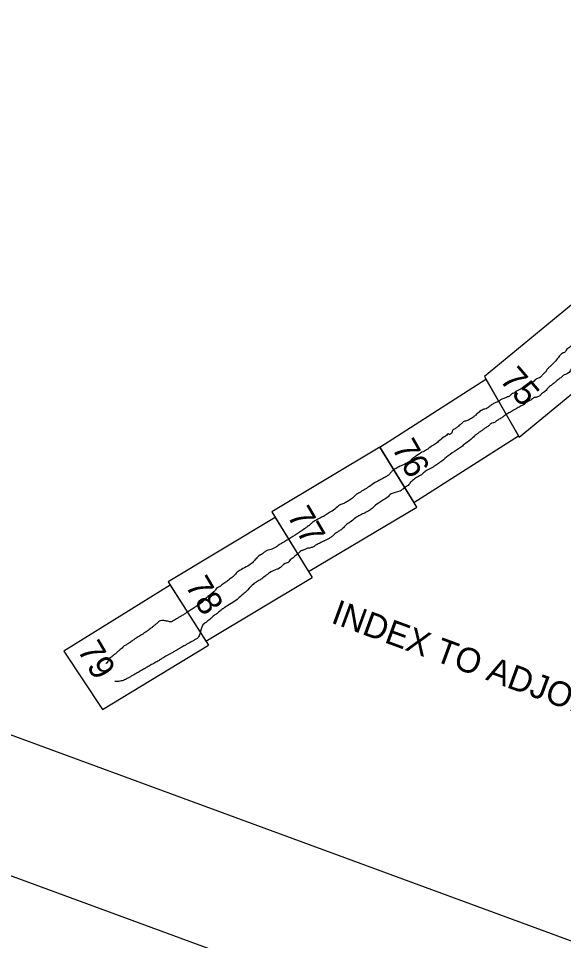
# Model space of a CAD drawing. Extents: x 3972907 to 3994831, y 172639 to 190852.
# Drawn here: x 3984065 to 3985354, y 175090 to 177268 of the extents above; entities that cross this region are included whole.
import ezdxf

# ---------------------------------------------------------------- set-up
doc = ezdxf.new("R2010")
doc.units = 0
for name, color, linetype in [('G-ANNO-NPLT', 7, 'Continuous'), ('V-ANNO-NPLT', 7, 'Continuous'), ('V-ANNO-SYMB', 7, 'Continuous')]:
    doc.layers.add(name, color=color, linetype=linetype)

msp = doc.modelspace()

# ---------------------------------------------------------------- linework, layer by layer
at = {"layer": 'G-ANNO-NPLT'}
msp.add_lwpolyline([(3973180.8, 179237.2), (3990388.6, 172912.5), (3994557.2, 184254), (3977349.3, 190578.7)], close=True, dxfattribs=at)
at = {"layer": 'V-ANNO-NPLT'}
msp.add_line((3984424, 175929.3), (3984514.7, 175787.9), dxfattribs=at)
for points in [[(3985380.7, 176598.4), (3985166.5, 176422.1)], [(3985166.5, 176422.1), (3985248.9, 176278.6), (3985484.6, 176472.4)], [(3984919.3, 176255), (3985170.1, 176415.7)], [(3985170.1, 176415.7), (3985247, 176281.9)], [(3985000.1, 176124.3), (3985247, 176281.9)], [(3984919.3, 176255), (3984663.9, 176102.4)], [(3984919.3, 176255), (3985000.1, 176124.3)], [(3985006.9, 176113.3), (3984919.3, 176255)], [(3984663.9, 176102.4), (3984751.1, 175961.5), (3985006.9, 176113.3)], [(3984672.3, 176088.9), (3984418.9, 175937.2), (3984508.6, 175797.3)], [(3984672.3, 176088.9), (3984759.7, 175947.5)], [(3984508.6, 175797.3), (3984759.7, 175947.5)], [(3984424, 175929.3), (3984172.6, 175773.6), (3984264, 175635.8), (3984514.7, 175787.9)]]:
    msp.add_lwpolyline(points, dxfattribs=at)
for points in [[(3985434, 176533.4), (3985420.3, 176525.3), (3985408.3, 176518.6), (3985397.9, 176512.2), (3985387.7, 176506.3), (3985376.4, 176497.7), (3985368.1, 176491.6), (3985359.8, 176484.3), (3985358.1, 176481.1), (3985352.3, 176477.8), (3985349, 176475.7), (3985342.4, 176468.8), (3985335.4, 176459.6), (3985321.4, 176445.2)], [(3985479, 176514.4), (3985471.9, 176511.3), (3985466.6, 176509.3), (3985460, 176505), (3985447.3, 176499), (3985438.6, 176492), (3985429.2, 176488.2), (3985423.4, 176483.5), (3985419.1, 176481.2), (3985416.3, 176479.3), (3985408.7, 176472.3), (3985401.5, 176466.7), (3985394.6, 176460.4), (3985388.1, 176455), (3985382.3, 176450.3), (3985378.2, 176445), (3985375.1, 176440.7), (3985372, 176440.4), (3985370.5, 176439), (3985369.1, 176435.6), (3985353.6, 176425)], [(3985321.4, 176445.2), (3985315.8, 176440.1), (3985311.4, 176433.6), (3985306.8, 176429.4), (3985302, 176423.8), (3985299.2, 176420.4), (3985293.5, 176418.1), (3985290.7, 176416.6), (3985281.6, 176409.7), (3985272.9, 176404.5), (3985268.3, 176402.2), (3985262.7, 176398.3), (3985255, 176393.9), (3985249.9, 176391.4), (3985238.9, 176385.2), (3985235.8, 176383), (3985232.3, 176381.7), (3985227.1, 176377), (3985220.7, 176373.9), (3985212.2, 176370.1), (3985207.8, 176368.5)], [(3985353.6, 176425), (3985347, 176419.4), (3985339.5, 176413.7), (3985333.5, 176408.6), (3985329.1, 176405.1), (3985322.7, 176400.1), (3985315.1, 176392.9), (3985312.3, 176389.5), (3985308.3, 176386.2), (3985303.8, 176383.1), (3985298.3, 176377.8), (3985296.2, 176376), (3985292.1, 176374.2), (3985288.5, 176372.6), (3985285.1, 176372.5), (3985280.1, 176369.2), (3985276.1, 176366.6), (3985268.6, 176362.8), (3985264.9, 176360.9), (3985261.8, 176357.6), (3985255.5, 176354), (3985250.8, 176351.4)], [(3985250.8, 176351.4), (3985241.5, 176346.1), (3985235, 176342.5), (3985230.6, 176339.6), (3985222.2, 176334.9), (3985212.8, 176328.7), (3985205.7, 176323.6), (3985197.9, 176319.1), (3985193.1, 176315.3), (3985187, 176312.6), (3985182, 176310.8), (3985176.3, 176305.5), (3985170, 176301.4), (3985163.6, 176296.9), (3985158.3, 176292.9), (3985150.8, 176287.9), (3985147.5, 176285.5), (3985142.6, 176281.2)], [(3985158.2, 176341.9), (3985163.8, 176345), (3985167.9, 176346), (3985172.7, 176347.9), (3985177.1, 176350.9)], [(3985207.8, 176368.5), (3985195.8, 176361.9), (3985188.4, 176358.3), (3985180.8, 176353.3), (3985177.1, 176350.9)], [(3985158.2, 176341.9), (3985153.9, 176338.1), (3985146.1, 176331.3), (3985140.5, 176326.4), (3985133.7, 176322.1), (3985129.3, 176319.1), (3985124.4, 176317.3), (3985119.9, 176316.7), (3985116.5, 176315.2), (3985114.1, 176312.4), (3985107.3, 176307.1), (3985103.4, 176303.3), (3985100.6, 176301.3), (3985097.1, 176298.9)], [(3985097.1, 176298.9), (3985090.4, 176293.1), (3985089.9, 176290.1), (3985089.3, 176289.1), (3985087.4, 176287.2), (3985085.8, 176285.9), (3985084.3, 176284.9), (3985083.7, 176284.8), (3985081.5, 176286.8), (3985080.8, 176286.9), (3985076.9, 176283.2), (3985071.8, 176279.6)], [(3985071.6, 176279.7), (3985059.5, 176270.3), (3985051.2, 176263.2), (3985040.5, 176256.6), (3985030.1, 176249.1), (3985019, 176243.2), (3985002.7, 176232.6), (3984997.1, 176228.7), (3984990.4, 176221.8), (3984981, 176216.6), (3984970.1, 176211.4), (3984960.1, 176206.5), (3984951.2, 176201.1)], [(3985142.6, 176281.2), (3985134.7, 176273.8), (3985118.8, 176261.4), (3985110.1, 176254.6), (3985100.8, 176248), (3985080.7, 176234.8), (3985065.8, 176222.3), (3985055.6, 176215.4), (3985045.5, 176208.5), (3985026.6, 176198.2), (3985019.3, 176191.6), (3985012.9, 176187.3), (3985006.1, 176183.8), (3985001.3, 176180.3), (3984992.2, 176172.3), (3984986, 176165.2), (3984978.3, 176159.6)], [(3984951.2, 176201.1), (3984945.3, 176195.5), (3984939.9, 176189.6), (3984933.4, 176185.4), (3984924.6, 176180.2), (3984914.7, 176175.4), (3984908.6, 176172.2), (3984893.4, 176161.5), (3984882.1, 176154.8), (3984870.7, 176147.5), (3984862.7, 176142.7), (3984856.8, 176137), (3984848.1, 176130.5), (3984838.4, 176124.4), (3984829.7, 176121), (3984819.2, 176114.6), (3984806.5, 176104.2), (3984802.8, 176102.5), (3984800.4, 176101), (3984790.5, 176094.4), (3984781.9, 176089.7), (3984770.3, 176083.7), (3984760.9, 176078.6)], [(3984978.3, 176159.6), (3984966.4, 176151.6), (3984945.9, 176144.8), (3984936.4, 176136.2), (3984925.7, 176129.3), (3984916, 176123.2), (3984902.6, 176112.4), (3984895.9, 176106.4), (3984884.4, 176100.4), (3984873, 176094.9), (3984861.8, 176088.2), (3984849.4, 176078.3), (3984839.2, 176071.2), (3984831.4, 176063.2), (3984824.2, 176057.9)], [(3984760.9, 176078.6), (3984756.5, 176074), (3984750.6, 176069.3), (3984743.7, 176064.1), (3984733.4, 176056.6), (3984714.2, 176044.4), (3984703.9, 176037.9), (3984694.9, 176032.9)], [(3984787.9, 176034), (3984794.2, 176037), (3984800.6, 176040.7), (3984806.5, 176044.8), (3984812.9, 176050.3)], [(3984824.2, 176057.9), (3984818.1, 176053.8), (3984812.9, 176050.3)], [(3984695.1, 176033), (3984684, 176026), (3984675, 176020.1), (3984669.3, 176016.8), (3984662.2, 176014), (3984648.3, 176008.6), (3984642.3, 176003.8), (3984633, 175997.8), (3984625, 175989.8), (3984618.8, 175982.5), (3984607.3, 175974.7), (3984592.2, 175966.4)], [(3984787.9, 176034), (3984786.9, 176033.6), (3984779.9, 176030), (3984771.6, 176025.8), (3984767.7, 176023.6), (3984764.3, 176020.4), (3984757.5, 176018.2), (3984753.3, 176016.9), (3984750.3, 176016.9), (3984743.8, 176014.6), (3984739.8, 176012.8), (3984733.2, 176010.2), (3984726.6, 176004.6)], [(3984726.6, 176004.6), (3984716.4, 175995.5), (3984712.5, 175992.2), (3984707.3, 175989.4), (3984704.3, 175984.6), (3984695.7, 175980.5), (3984680.6, 175968.5), (3984672.8, 175965.6), (3984659, 175958.7), (3984637.6, 175942.8), (3984633.6, 175940.3), (3984628.3, 175937.1), (3984621.9, 175933)], [(3984592.2, 175966.4), (3984582.4, 175960), (3984574.3, 175951.2), (3984571.4, 175948.4), (3984561.9, 175941.6), (3984553.1, 175934.9), (3984544.2, 175928.6), (3984538.3, 175924.4), (3984533.8, 175922.2), (3984530.7, 175918), (3984513.2, 175902.7), (3984499.6, 175889.5), (3984491.8, 175882.9), (3984487.7, 175880.5), (3984482.4, 175877.2)], [(3984749.9, 175963.2), (3984750.4, 175963.1), (3984750.9, 175962.6), (3984751.2, 175962.3), (3984751.6, 175961.8)], [(3984621.9, 175933), (3984613.8, 175925.8), (3984600.9, 175912), (3984592.3, 175904.9), (3984582.2, 175895.5), (3984568.2, 175886.5), (3984551.8, 175875.8), (3984544.3, 175870.5), (3984536.5, 175864.1), (3984529.8, 175859.1)], [(3984482.4, 175877.2), (3984478.3, 175874.4), (3984474.1, 175871.9), (3984464.5, 175865.6)], [(3984464.5, 175865.6), (3984461.2, 175863.5), (3984456.8, 175860.6), (3984453.6, 175858.7), (3984449.8, 175856.2), (3984445, 175853.6), (3984438.8, 175849.8), (3984433.8, 175846.9), (3984430.4, 175844.9), (3984427.4, 175842.9), (3984420.7, 175843.7), (3984415.5, 175844.6), (3984411.7, 175845.4), (3984406.9, 175845.9)], [(3984529.8, 175859.1), (3984522, 175852.6), (3984517.1, 175848.3), (3984513.1, 175845.5), (3984508.1, 175841.3), (3984505.6, 175839.8), (3984495.4, 175817.3)], [(3984406.9, 175845.9), (3984401.4, 175845.6), (3984398.9, 175844.8), (3984394.5, 175841), (3984388.8, 175836.1), (3984383.5, 175831.9), (3984378.5, 175827.6), (3984374.5, 175824.4), (3984369.4, 175820.9), (3984361.6, 175815.7), (3984356.5, 175812.4)], [(3984356.5, 175812.4), (3984345.9, 175805.9), (3984335.2, 175798.8), (3984327, 175793), (3984320.5, 175788.9), (3984314, 175784.6), (3984312.4, 175782.8)], [(3984495.4, 175817.3), (3984493.3, 175812.4), (3984491.2, 175807.4), (3984489.5, 175805.1), (3984482.7, 175800.8), (3984477.1, 175797.4), (3984469.6, 175793.2), (3984463.5, 175789.8), (3984456.9, 175786.1), (3984456.3, 175785.8)], [(3984456.3, 175785.8), (3984447.5, 175780.7), (3984441.8, 175777.3), (3984433.8, 175772.9), (3984426.6, 175768.5), (3984422.3, 175766.2), (3984416.6, 175763), (3984406.3, 175757.2), (3984398.9, 175752.5), (3984396.6, 175751.1)], [(3984312.4, 175782.8), (3984303.6, 175775.5), (3984298.5, 175771), (3984293.4, 175766.6), (3984288.3, 175762.6), (3984283.6, 175758.5), (3984279.6, 175755.3), (3984278.9, 175753.9), (3984277.5, 175751.1), (3984275.4, 175747.1), (3984274.8, 175745.9), (3984273.7, 175745.2), (3984272, 175744.7)], [(3984396.6, 175751.1), (3984388, 175746.2), (3984377.1, 175740.2), (3984369.7, 175736), (3984361.1, 175730.9), (3984350.3, 175724.8), (3984341.7, 175719.9)], [(3984341.7, 175719.9), (3984335.1, 175716.1), (3984328.3, 175712.2), (3984322.2, 175708.7), (3984318.3, 175706.9), (3984313.7, 175704.4), (3984308, 175703.3), (3984302.4, 175702.3), (3984297, 175702.1), (3984293.4, 175702.2)]]:
    msp.add_spline(points, degree=3, dxfattribs=at)
at = {"layer": 'V-ANNO-SYMB'}
msp.add_lwpolyline([(3974579.2, 179056.1), (3990105.3, 173349.5), (3994058.3, 184104.4), (3978532.2, 189811), (3974579.2, 179056.1)], dxfattribs=at)

# ---------------------------------------------------------------- texts
at = {"layer": 'V-ANNO-NPLT'}
for s, height, rotation, p in [('75', 58.5, 310.531, (3985200.6, 176413.8)), ('76', 58.5, 299.531, (3984946.4, 176253.9)), ('77', 58.5, 300.531, (3984698.9, 176093.9)), ('78', 58.5, 300.531, (3984458.2, 175928.9)), ('INDEX TO ADJOINING SHEETS', 58.33, 339.8191, (3984801.6, 175841.5)), ('79', 58.5, 300.531, (3984203.3, 175776.6))]:
    msp.add_text(s, height=height, rotation=rotation, dxfattribs=at).set_placement(p)

doc.saveas('drawing.dxf')
